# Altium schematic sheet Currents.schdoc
size 313 x 206 mm
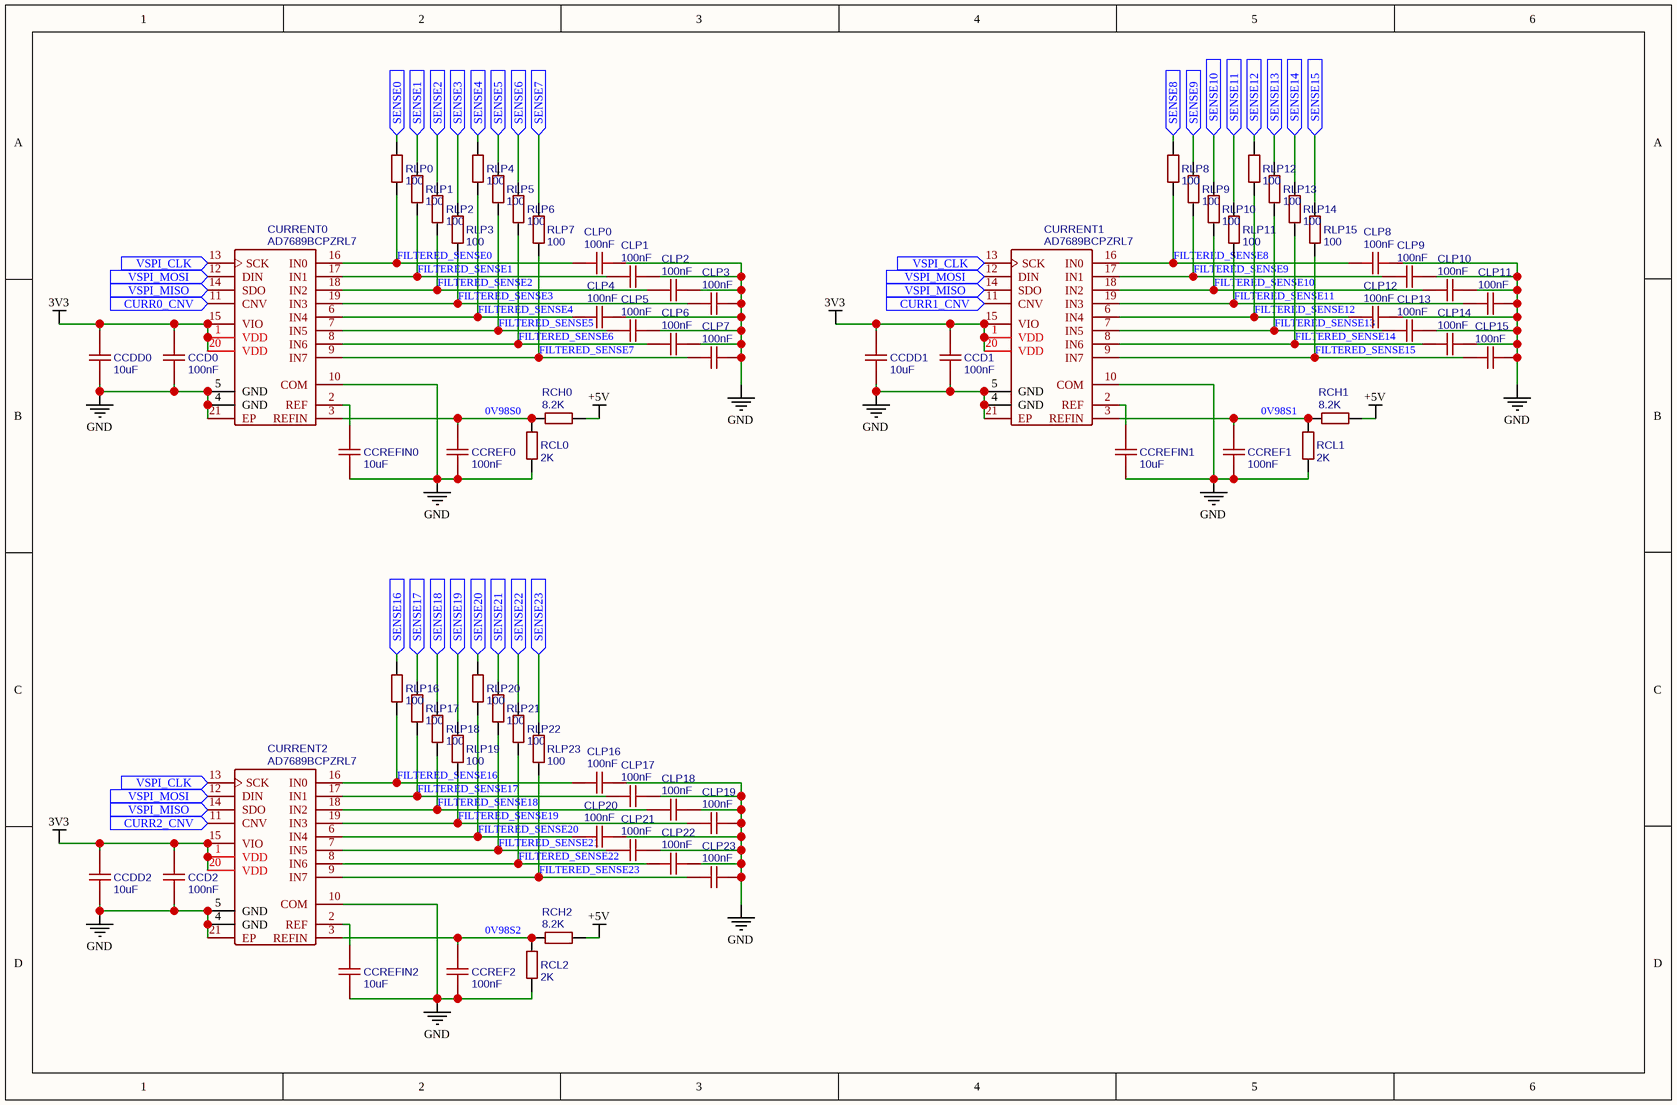
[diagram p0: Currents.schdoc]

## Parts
CCD0  100nF  [0603]
CCD1  100nF  [0603]
CCD2  100nF  [0603]
CCDD0  10uF  [0603]
CCDD1  10uF  [0603]
CCDD2  10uF  [0603]
CCREF0  100nF  [0603]
CCREF1  100nF  [0603]
CCREF2  100nF  [0603]
CCREFIN0  10uF  [0603]
CCREFIN1  10uF  [0603]
CCREFIN2  10uF  [0603]
CLP0  100nF  [0603]
CLP1  100nF  [0603]
CLP2  100nF  [0603]
CLP3  100nF  [0603]
CLP4  100nF  [0603]
CLP5  100nF  [0603]
CLP6  100nF  [0603]
CLP7  100nF  [0603]
CLP8  100nF  [0603]
CLP9  100nF  [0603]
CLP10  100nF  [0603]
CLP11  100nF  [0603]
CLP12  100nF  [0603]
CLP13  100nF  [0603]
CLP14  100nF  [0603]
CLP15  100nF  [0603]
CLP16  100nF  [0603]
CLP17  100nF  [0603]
CLP18  100nF  [0603]
CLP19  100nF  [0603]
CLP20  100nF  [0603]
CLP21  100nF  [0603]
CLP22  100nF  [0603]
CLP23  100nF  [0603]
CURRENT0  AD7689BCPZRL7  [LFCSP-20-DOT-TOP-LEFT]
CURRENT1  AD7689BCPZRL7  [LFCSP-20-DOT-TOP-LEFT]
CURRENT2  AD7689BCPZRL7  [LFCSP-20-DOT-TOP-LEFT]
RCH0  8.2K  [0603]
RCH1  8.2K  [0603]
RCH2  8.2K  [0603]
RCL0  2K  [0603]
RCL1  2K  [0603]
RCL2  2K  [0603]
RLP0  100  [0603]
RLP1  100  [0603]
RLP2  100  [0603]
RLP3  100  [0603]
RLP4  100  [0603]
RLP5  100  [0603]
RLP6  100  [0603]
RLP7  100  [0603]
RLP8  100  [0603]
RLP9  100  [0603]
RLP10  100  [0603]
RLP11  100  [0603]
RLP12  100  [0603]
RLP13  100  [0603]
RLP14  100  [0603]
RLP15  100  [0603]
RLP16  100  [0603]
RLP17  100  [0603]
RLP18  100  [0603]
RLP19  100  [0603]
RLP20  100  [0603]
RLP21  100  [0603]
RLP22  100  [0603]
RLP23  100  [0603]

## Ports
CURR0_CNV, CURR1_CNV, CURR2_CNV, SENSE0, SENSE1, SENSE2, SENSE3, SENSE4, SENSE5, SENSE6, SENSE7, SENSE8, SENSE9, SENSE10, SENSE11, SENSE12, SENSE13, SENSE14, SENSE15, SENSE16, SENSE17, SENSE18, SENSE19, SENSE20, SENSE21, SENSE22, SENSE23, VSPI_CLK, VSPI_MISO, VSPI_MOSI

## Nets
3V3: CCD0.1 CCD1.1 CCD2.1 CCDD0.2 CCDD1.2 CCDD2.2 CURRENT0.1(VDD) CURRENT0.15(VIO) CURRENT0.20(VDD) CURRENT1.1(VDD) CURRENT1.15(VIO) CURRENT1.20(VDD) CURRENT2.1(VDD) CURRENT2.15(VIO) CURRENT2.20(VDD)
+5V: RCH0.1 RCH1.1 RCH2.1
GND: CCD0.2 CCD1.2 CCD2.2 CCDD0.1 CCDD1.1 CCDD2.1 CCREF0.2 CCREF1.2 CCREF2.2 CCREFIN0.1 CCREFIN1.1 CCREFIN2.1 CLP0.1 CLP1.2 CLP2.2 CLP3.2 CLP4.2 CLP5.2 CLP6.2 CLP7.2 CLP8.2 CLP9.2 CLP10.2 CLP11.2 CLP12.2 CLP13.2 CLP14.2 CLP15.1 CLP16.2 CLP17.2 CLP18.2 CLP19.2 CLP20.1 CLP21.2 CLP22.2 CLP23.2 CURRENT0.4(GND) CURRENT0.5(GND) CURRENT0.10(COM) CURRENT0.21(EP) CURRENT1.4(GND) CURRENT1.5(GND) CURRENT1.10(COM) CURRENT1.21(EP) CURRENT2.4(GND) CURRENT2.5(GND) CURRENT2.10(COM) CURRENT2.21(EP) RCL0.1 RCL1.1 RCL2.1
0V98S0: CCREF0.1 CURRENT0.3(REFIN) RCH0.2 RCL0.2
0V98S1: CCREF1.1 CURRENT1.3(REFIN) RCH1.2 RCL1.2
0V98S2: CCREF2.1 CURRENT2.3(REFIN) RCH2.2 RCL2.2
CURR0_CNV: CURRENT0.11(CNV) ; port CURR0_CNV
CURR1_CNV: CURRENT1.11(CNV) ; port CURR1_CNV
CURR2_CNV: CURRENT2.11(CNV) ; port CURR2_CNV
FILTERED_SENSE0: CLP0.2 CURRENT0.16(IN0) RLP0.1
FILTERED_SENSE1: CLP1.1 CURRENT0.17(IN1) RLP1.2
FILTERED_SENSE2: CLP2.1 CURRENT0.18(IN2) RLP2.2
FILTERED_SENSE3: CLP3.1 CURRENT0.19(IN3) RLP3.2
FILTERED_SENSE4: CLP4.1 CURRENT0.6(IN4) RLP4.2
FILTERED_SENSE5: CLP5.1 CURRENT0.7(IN5) RLP5.2
FILTERED_SENSE6: CLP6.1 CURRENT0.8(IN6) RLP6.2
FILTERED_SENSE7: CLP7.1 CURRENT0.9(IN7) RLP7.2
FILTERED_SENSE8: CLP8.1 CURRENT1.16(IN0) RLP8.2
FILTERED_SENSE9: CLP9.1 CURRENT1.17(IN1) RLP9.2
FILTERED_SENSE10: CLP10.1 CURRENT1.18(IN2) RLP10.2
FILTERED_SENSE11: CLP11.1 CURRENT1.19(IN3) RLP11.2
FILTERED_SENSE12: CLP12.1 CURRENT1.6(IN4) RLP12.2
FILTERED_SENSE13: CLP13.1 CURRENT1.7(IN5) RLP13.2
FILTERED_SENSE14: CLP14.1 CURRENT1.8(IN6) RLP14.2
FILTERED_SENSE15: CLP15.2 CURRENT1.9(IN7) RLP15.1
FILTERED_SENSE16: CLP16.1 CURRENT2.16(IN0) RLP16.2
FILTERED_SENSE17: CLP17.1 CURRENT2.17(IN1) RLP17.2
FILTERED_SENSE18: CLP18.1 CURRENT2.18(IN2) RLP18.2
FILTERED_SENSE19: CLP19.1 CURRENT2.19(IN3) RLP19.2
FILTERED_SENSE20: CLP20.2 CURRENT2.6(IN4) RLP20.2
FILTERED_SENSE21: CLP21.1 CURRENT2.7(IN5) RLP21.2
FILTERED_SENSE22: CLP22.1 CURRENT2.8(IN6) RLP22.2
FILTERED_SENSE23: CLP23.1 CURRENT2.9(IN7) RLP23.1
SENSE0: RLP0.2 ; port SENSE0
SENSE1: RLP1.1 ; port SENSE1
SENSE2: RLP2.1 ; port SENSE2
SENSE3: RLP3.1 ; port SENSE3
SENSE4: RLP4.1 ; port SENSE4
SENSE5: RLP5.1 ; port SENSE5
SENSE6: RLP6.1 ; port SENSE6
SENSE7: RLP7.1 ; port SENSE7
SENSE8: RLP8.1 ; port SENSE8
SENSE9: RLP9.1 ; port SENSE9
SENSE10: RLP10.1 ; port SENSE10
SENSE11: RLP11.1 ; port SENSE11
SENSE12: RLP12.1 ; port SENSE12
SENSE13: RLP13.1 ; port SENSE13
SENSE14: RLP14.1 ; port SENSE14
SENSE15: RLP15.2 ; port SENSE15
SENSE16: RLP16.1 ; port SENSE16
SENSE17: RLP17.1 ; port SENSE17
SENSE18: RLP18.1 ; port SENSE18
SENSE19: RLP19.1 ; port SENSE19
SENSE20: RLP20.1 ; port SENSE20
SENSE21: RLP21.1 ; port SENSE21
SENSE22: RLP22.1 ; port SENSE22
SENSE23: RLP23.2 ; port SENSE23
VSPI_CLK: CURRENT0.13(SCK) CURRENT1.13(SCK) CURRENT2.13(SCK) ; port VSPI_CLK
VSPI_MISO: CURRENT0.14(SDO) CURRENT1.14(SDO) CURRENT2.14(SDO) ; port VSPI_MISO
VSPI_MOSI: CURRENT0.12(DIN) CURRENT1.12(DIN) CURRENT2.12(DIN) ; port VSPI_MOSI
NetCCREFIN0_2: CCREFIN0.2 CURRENT0.2(REF)
NetCCREFIN1_2: CCREFIN1.2 CURRENT1.2(REF)
NetCCREFIN2_2: CCREFIN2.2 CURRENT2.2(REF)

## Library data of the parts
CCD0-CCD2 CCREF0-CCREF2 CLP0-CLP23 = 100nF: BOM_Manufacturer: YAGEO; BOM_Manufacturer Part: CC0603KRX7R9BB104; nameAlias: Capacitance; SMT Type: Basic
CCDD0-CCDD2 CCREFIN0-CCREFIN2 = 10uF: BOM_Manufacturer: SAMSUNG; BOM_Manufacturer Part: CL10A106KP8NNNC; nameAlias: Capacitance; SMT Type: Basic
CURRENT0-CURRENT2 = AD7689BCPZRL7: BOM_Manufacturer: ADI
RCH0-RCH2 = 8.2K: BOM_Manufacturer: UniOhm; BOM_Manufacturer Part: 0603WAF8201T5E; nameAlias: Resistance (Ohms); SMT Type: Basic
RCL0-RCL2 = 2K: BOM_Manufacturer: UniOhm; BOM_Manufacturer Part: 0603WAF2001T5E; nameAlias: Resistance (Ohms); SMT Type: Basic
RLP0-RLP23 = 100: BOM_Manufacturer: UniOhm; BOM_Manufacturer Part: 0603WAF1000T5E; nameAlias: Resistance (Ohms); SMT Type: Basic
